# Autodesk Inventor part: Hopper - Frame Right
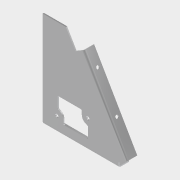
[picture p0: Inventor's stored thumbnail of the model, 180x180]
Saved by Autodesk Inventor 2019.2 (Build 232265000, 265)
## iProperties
Created: 2005-11
Part Number: Hopper - Frame Right
Document SubType Name: Sheet Metal
Designer: floress
Material: Aluminum 6061
Density: 2.7 g/cm^3
Sheet Metal Rule: Default
Appearance: Aluminum - Flat
Flat Pattern Width: 12.2582 cm
Flat Pattern Length: 14.0116 cm
Flat Pattern Area: 171.757 cm^2
Sheet Metal Width: 4.826 in
Sheet Metal Length: 5.516 in
Sheet Metal Area: 26.622 in^2
Author: floress
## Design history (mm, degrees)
node "Face1"
node "Flange1"
node "Flange2"
sketch "Sketch4"
  geometry: L1 (0, 0)-(0, 11.112) reference; L2 (101.6, 11.113)-(101.6, 0) reference; C1 r 1.778 at (12.7, 5.556); C2 r 1.778 at (88.9, 5.556); 1 further point
  constraints: 2 centre point, 2 horizontal alignment, 1 equal radius, 1 midpoint
  dimensions: "d21" = 3.556 diameter of C1; "d22" = 12.7 distance from line of L1 C1.centre; "d23" = 12.7 distance from line of L2 C2.centre
cut "Cut1" sketch "Sketch4" dims "d24" = 1.5875 (= Thickness), "d25" = 0
cut "Cut2" dims "d27" = 1.5875 (= Thickness), "d28" = 0
cut "Cut3" dims "d35" = 3.175 (= 2 x Thickness), "d36" = 0
body "Solid1"
sketch "Sketch1"
  geometry: L1 (-65.393, 63.5)-(-34.328, 63.5); L2 (36.207, -63.5)-(-65.393, -63.5); L3 (-65.393, -63.5)-(-65.393, 63.5); L4 (-34.328, 63.5)-(-21.628, 41.503); L5 (-21.628, 41.503)-(-10.63, 47.853); L6 (-10.63, 47.853)-(47.205, -52.321); L7 (36.207, -63.5)-(36.207, -58.671); L8 (36.207, -58.671)-(47.205, -52.321); 3 further points
  constraints: 16 end point, 4 parallel, 3 perpendicular, 1 horizontal, 1 horizontal alignment, 1 midpoint, 1 vertical alignment
  dimensions: "d1" = 127 distance of L2.end L1.start; "d2" = 12.7 distance of L4.end L5.end; "d3" = 25.4 distance of L1.end L4.end; "d4" = 60 deg angle of L2 L6; "d20" = 101.6 distance of L2.start L2.end
face "Plate1" dims "d37" = 1.5875 (= Thickness)
sketch "Sketch2"
  geometry: L1 through (-50.8, 0) direction (-1, 0); L2 (-101.6, 0)-(-101.6, -12.7); L3 (-101.6, -12.7)-(0, -12.7); L4 through (0, -6.35) direction (0, 1)
  constraints: 6 end point, 1 horizontal, 1 perpendicular, 1 vertical
face "Plate2" dims "d6" = 1.5875 (= BendReliefWidth), "d8" = 3.175 (= MinimumRemnant), "d10" = 12.7, "d11" = 90 deg, "d12" = 1.5875 (= BendRadius), "d37" = 1.5875 (= Thickness)
bend "Bend1" dims "d6" = 1.5875 (= BendReliefWidth), "d7" = 0.79375 (= BendReliefDepth), "d8" = 3.175 (= MinimumRemnant), "d9" = 1.5875 (= BendRadius), "d10" = 12.7, "d11" = 90 deg, "d12" = 1.5875 (= BendRadius), "d37" = 1.5875 (= Thickness), "SeamGap" = 0.00508
sketch "Sketch3"
  geometry: L1 through (-57.835, 0) direction (-1, -4.26e-33); L2 (-115.67, 0)-(-115.67, -12.7); L3 (-115.67, -12.7)-(0, -12.7); L4 through (0, -6.35) direction (3.08e-33, 1)
  constraints: 6 end point, 1 horizontal, 1 perpendicular, 1 vertical
face "Plate3" dims "d13" = 1.5875 (= BendReliefWidth), "d15" = 3.175 (= MinimumRemnant), "d17" = 12.7, "d18" = 90 deg, "d19" = 1.5875 (= BendRadius), "d37" = 1.5875 (= Thickness)
bend "Bend2" dims "d13" = 1.5875 (= BendReliefWidth), "d14" = 0.79375 (= BendReliefDepth), "d15" = 3.175 (= MinimumRemnant), "d16" = 1.5875 (= BendRadius), "d17" = 12.7, "d18" = 90 deg, "d19" = 1.5875 (= BendRadius), "d37" = 1.5875 (= Thickness), "SeamGap" = 0.00508
sketch "Sketch5"
  geometry: L1 (0, 0)-(11.112, 0) reference; C1 r 2.159 at (5.556, -21.346); C2 r 2.159 at (5.556, -72.84); 1 further point
  constraints: 2 centre point, 2 vertical alignment, 1 equal radius, 1 midpoint
  dimensions: "d26" = 4.318 diameter of C1
sketch "Sketch6"
  geometry: L1 (-21.395, -91.558)-(-21.395, -87.095); L2 (-19.808, -85.508)-(9.363, -85.508); L3 (3.614, -109.411)-(3.614, -113.855); L4 (2.026, -115.443)-(-28.276, -115.443) reference; L5 (10.95, -87.095)-(10.95, -99.666); L6 (-29.864, -113.856)-(-29.864, -101.525) reference; L7 (-28.855, -100.047)-(-26.579, -99.155); L8 (9.942, -101.144)-(9.003, -101.511); C1 r 2.134 at (-29.555, -91.558); C2 r 2.134 at (12.097, -109.411); A1 r 1.587 centre (9.363, -87.095) between (10.95, -87.095) and (9.363, -85.508); A2 r 1.587 centre (-19.808, -87.095) between (-19.808, -85.508) and (-21.395, -87.095); A3 r 1.587 centre (-28.276, -113.856) between (-29.864, -113.856) and (-28.276, -115.443); A4 r 1.587 centre (2.026, -113.855) between (2.026, -115.443) and (3.614, -113.855); A5 r 1.587 centre (-28.276, -101.525) between (-28.855, -100.047) and (-29.864, -101.525); A6 r 1.587 centre (9.363, -99.666) between (9.942, -101.144) and (10.95, -99.666); A7 r 8.16 centre (-29.555, -91.558) between (-26.579, -99.155) and (-21.395, -91.558); A8 r 8.484 centre (12.097, -109.411) between (9.003, -101.511) and (3.614, -109.411); 2 further points
  constraints: 16 end point, 16 point on circle, 16 tangent, 10 centre point, 5 equal radius, 2 concentric, 2 parallel, 2 perpendicular, 2 point on line, 1 horizontal, 1 vertical, 1 other
  dimensions: "d29" = 4.2672 diameter of C1; "d34" = 1.5875 radius of A1; "d38" = 1.5875 radius of A5
feature "Definition1"
other parameters: "Thickness" = 1.5875, "BendRadius" = 1.5875 (= Thickness), "BendReliefWidth" = 1.5875 (= Thickness), "BendReliefDepth" = 0.79375 (= 0.5 x Thickness), "CornerReliefSize" = 6.35 (= 4 x Thickness), "MinimumRemnant" = 3.175 (= 2 x Thickness), "TransitionRadius" = 1.5875 (= BendRadius), "d5" = 1.5875 (= BendRadius), "JacobiRadiusSize" = 1.5875 (= Thickness), "GapSize" = 1.5875 (= Thickness), "BendRadius" = 1.5875, "BendReliefDepth" = 0.79375, "BendReliefWidth" = 1.5875, "CornerReliefSize" = 6.35, "GapSize" = 1.5875, "JacobiRadiusSize" = 1.5875, "MinimumRemnant" = 3.175, "Thickness" = 1.5875, "TransitionRadius" = 1.5875
